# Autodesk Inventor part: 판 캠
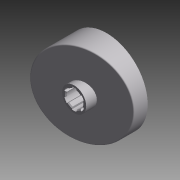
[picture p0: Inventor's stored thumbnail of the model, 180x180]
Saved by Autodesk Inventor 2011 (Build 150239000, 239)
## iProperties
Created: 2012-05
Part Number: 판 캠
Document SubType Name: 모델링
Designer: SeoGD™
Material: 강
Mass: 681.586 g
Surface Area: 331.304 cm^2
Volume: 86.8262 cm^3
Density: 7.85 g/cm^3
변환 표준: STEP AP214IS
파일 이름: C:\Users\SeoGD\Desktop\?쒗뿕\??stp
전처리기: Build: 253, Release: 2010 SP1 - Date: Wed 07/29/2009
전송 단위: 밀리미터
불확실성: 0.01
Author: SeoGD™
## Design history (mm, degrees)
node "작업 평면4"
sketch "스케치1"
  geometry: C1 r 44.5 at (0, 0); 1 further point
  constraints: 1 centre point, 1 coincident
  dimensions: "d25" = 89 diameter of C1
extrude "돌출1" new body sketch "스케치1" distance "d1" = 40; taper "d2" = 0 deg
sketch "스케치2"
  geometry: L1 (-44.5, 15)-(44.5, 38.847); L2 (-44.5, 0)-(-44.5, 40) reference; L3 (-44.5, 40)-(44.5, 40) reference; L4 (44.5, 0)-(44.5, 40) reference; 1 further point
  constraints: 2 end point, 2 point on line
  dimensions: "d26" = 15 distance of L2.start L1.start; "d27" = 75 deg angle of L1 L2
extrude "돌출2" cut sketch "스케치2" stored distance "d5" = 40; taper "d6" = 0 deg
node "작업 평면1"
sketch "스케치3"
  geometry: C1 r 13 at (0, 0); 1 further point
  constraints: 1 centre point, 1 coincident
  dimensions: "d9" = 26 diameter of C1
extrude "돌출3" join sketch "스케치3" distance "d10" = 38; taper "d11" = 0 deg
hole "구멍1" diameter "d14" = 18; stored, may be unused: countersink angle "d18" = 90 deg, drill point angle "d20" = 118 deg; dims "d12" = 10, "d13" = 10, "d15" = 6, "d16" = 4, "d17" = 2, "d19" = 8
feature "쉘2" dims "d29" = 5
sketch "스케치6"
  geometry: C1 r 17.5 at (0, 0); C2 r 14 at (0, 0) reference; 1 further point
  constraints: 1 centre point, 1 coincident
  dimensions: "d28" = 35 diameter of C1
extrude "돌출4" join sketch "스케치6" stored distance "d30" = 38; taper "d31" = 0 deg
fillet "모깎기1" dims "d32" = 3
chamfer "모따기1" distance "d21" = 1; stored, may be unused: second distance "d22" = 2, angle "d23" = 45 deg
sketch "스케치7"
  geometry: L1 (-12.374, 12.374)-(-27.931, 27.931); A1 r 39.5 centre (0, 0) between (-27.931, 27.931) and (0, 39.5) reference; 2 further points
  constraints: 2 end point, 2 point on circle, 1 point on line, 1 vertical alignment, 2 other
  dimensions: "d33" = 45 deg dimension on point (0, 0) L1.start A1.end
feature "리브1" sketch "스케치7" dims "d34" = 5, "d35" = 1, "d36" = 0
fillet "모깎기2" dims "d37" = 3
sketch "스케치8"
  geometry: L1 (2.5, 10.712)-(2.5, 8.646); L2 (-2.5, 10.712)-(-2.5, 8.646); A1 r 11 centre (0, 0) between (2.5, 10.712) and (-2.5, 10.712); A2 r 9 centre (0, 0) between (2.5, 8.646) and (-2.5, 8.646) reference; 1 further point
  constraints: 4 end point, 4 point on circle, 2 parallel, 1 centre point, 1 coincident, 1 vertical
  dimensions: "d41" = 22 diameter of A1; "d42" = 5 distance between parallel lines of L1 L2
extrude "돌출5" cut sketch "스케치8" stored distance "d43" = 38; taper "d44" = 0 deg
fillet "모깎기3" dims "d48" = 1
node "솔리드1"
node "솔리드 본체"
node "곡면 본체"
pattern_circular "원형 패턴1" dims angle "d39" = 360 deg
pattern_circular "원형 패턴2" dims angle "d46" = 360 deg
node "솔리드2"
